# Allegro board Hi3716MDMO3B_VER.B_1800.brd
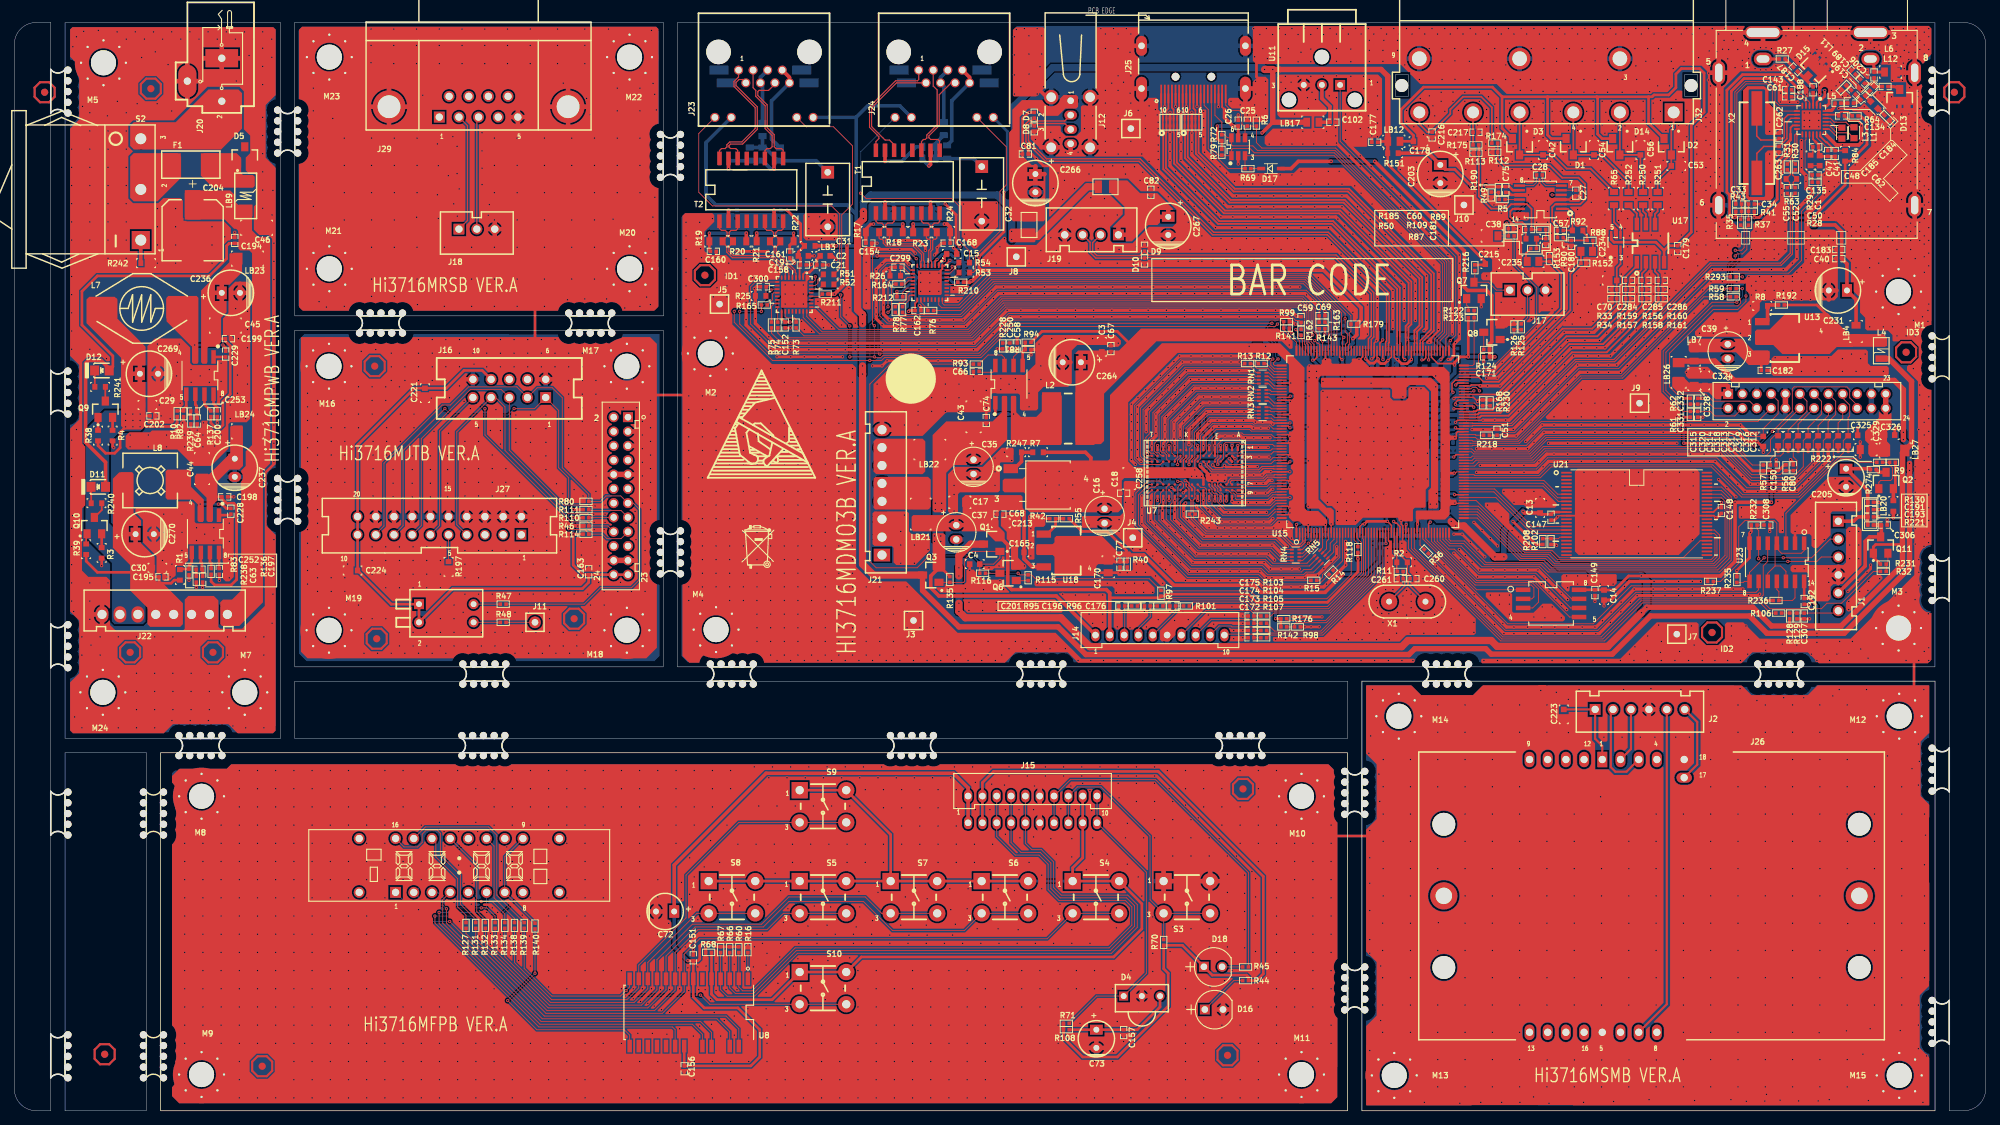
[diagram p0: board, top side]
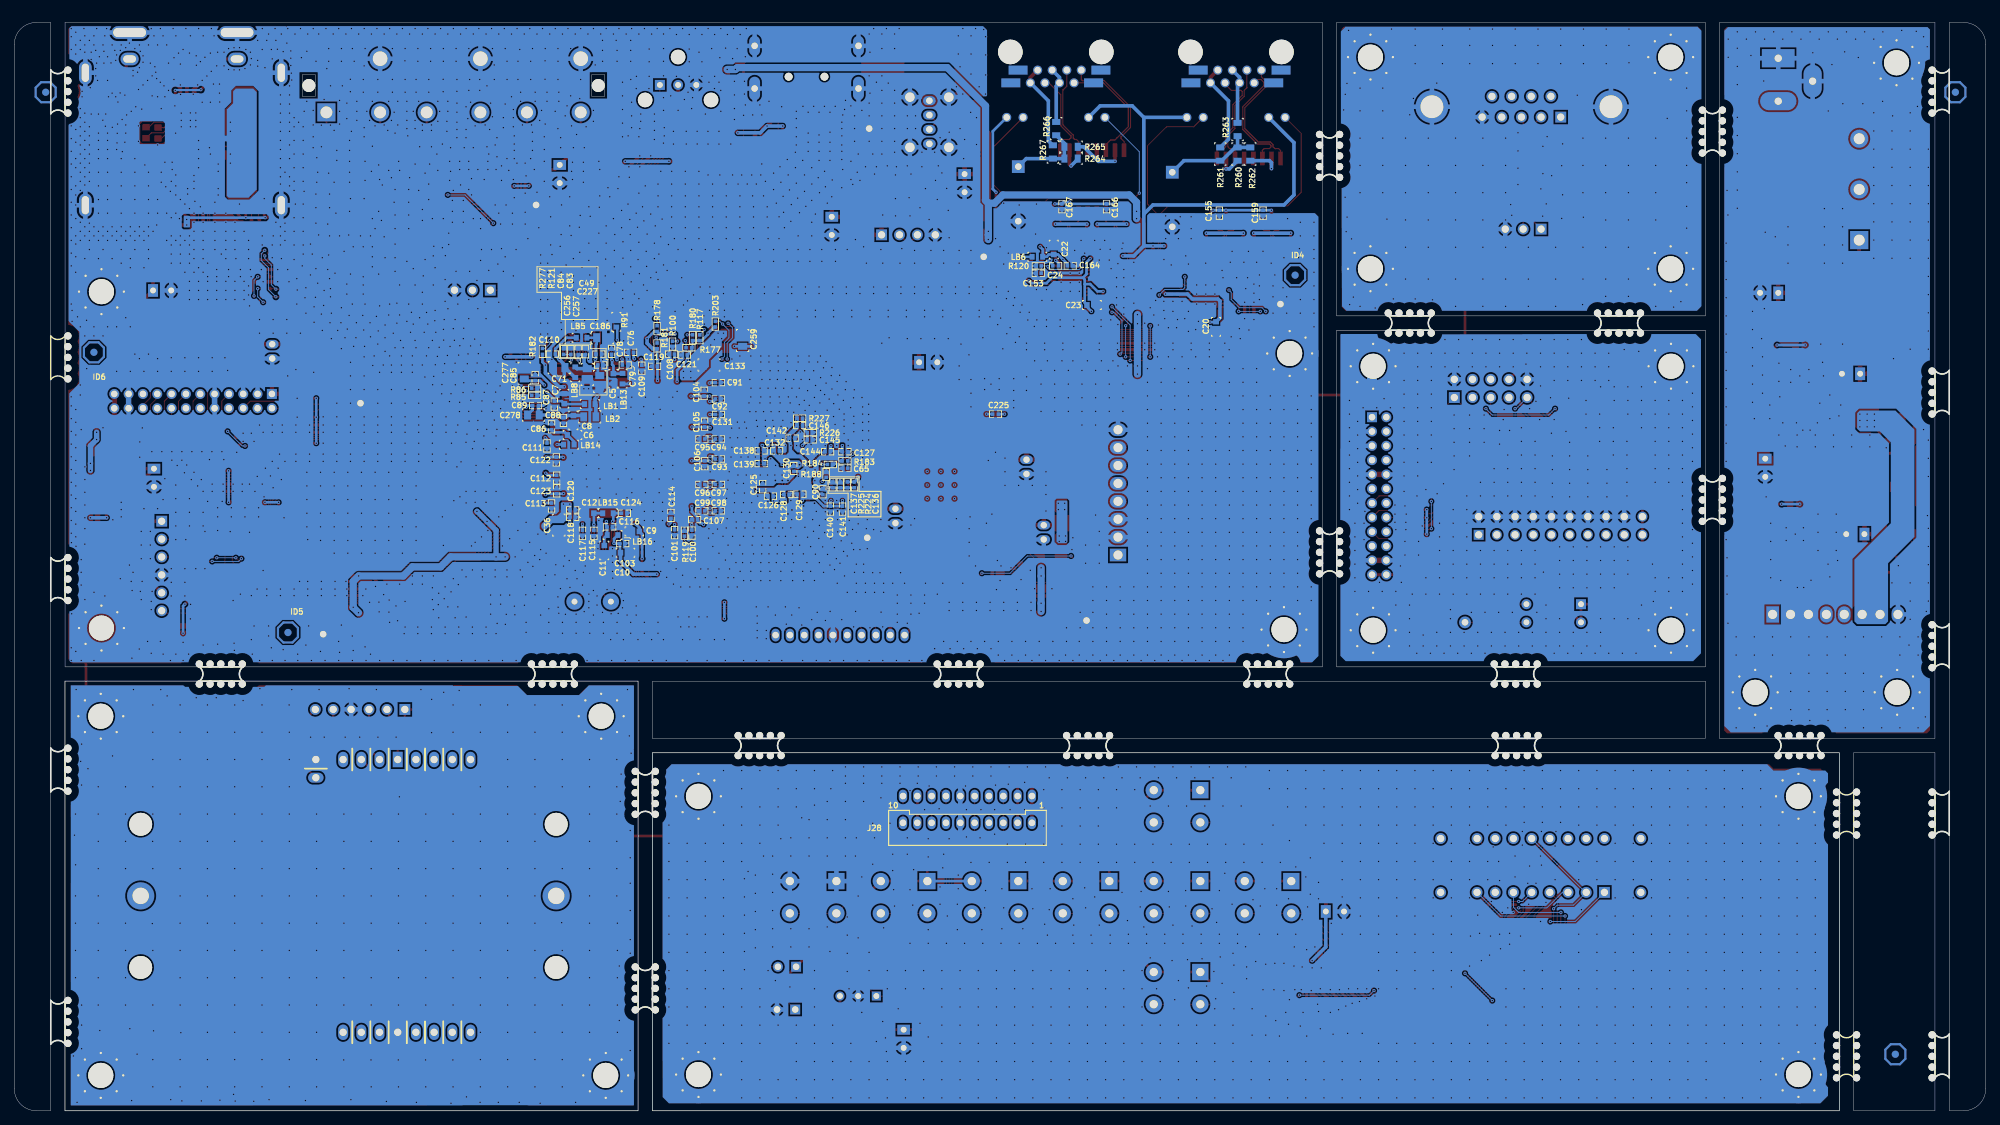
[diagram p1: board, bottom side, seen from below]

Outline 275.18 x 151.99 mm; copper layers: TOP, BOTTOM. Coordinates in mm from the lower left corner of the outline.

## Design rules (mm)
net group DIFFPAIR6: nets TMDS_CLK_N TMDS_CLK_P
net group DIFFPAIR7: nets DM_USB1 DP_USB1
net group DIFFPAIR8: nets DM_USB0 DP_USB0
net group DIFFPAIR10: nets QAM_VINN QAM_VINP
net group DIFFPAIR11: nets TX+_PHY0 TX-_PHY0
net group DIFFPAIR12: nets RX+_PHY0 RX-_PHY0
net group DIFFPAIR15: nets TX+_PHY1 TX-_PHY1
net group DIFFPAIR16: nets RX+_PHY1 RX-_PHY1
net group DIFFPAIR17: nets $12N115 $12N116
net group DIFFPAIR18: nets $12N91 $12N113
net group DIFFPAIR19: nets $12N126 $12N127
net group DIFFPAIR20: nets $12N124 $12N125
net group DIFFPAIR21: nets TMDS_D0_N TMDS_D0_P
net group DIFFPAIR22: nets TMDS_D1_N TMDS_D1_P
net group DIFFPAIR23: nets TMDS_D2_N TMDS_D2_P
net group DIFFPAIR24: nets $17N139 $17N140
net group DIFFPAIR25: nets $17N94 $17N549
net group DDR: nets DDR_ADDR0 DDR_ADDR0_A DDR_ADDR1 DDR_ADDR1_A DDR_ADDR2 DDR_ADDR2_A DDR_ADDR3 DDR_ADDR3_A DDR_ADDR4 DDR_ADDR4_A DDR_ADDR5 DDR_ADDR5_A DDR_ADDR6 DDR_ADDR6_A DDR_ADDR7 DDR_ADDR7_A DDR_ADDR8 DDR_ADDR8_A DDR_ADDR9 DDR_ADDR9_A DDR_ADDR10 DDR_ADDR10_A DDR_ADDR11 DDR_ADDR11_A DDR_ADDR12 DDR_ADDR12_A DDR_ADDR13 DDR_ADDR13_A DDR_ADDR14 DDR_ADDR14_A DDR_BA0 DDR_BA0_A DDR_BA1 DDR_BA1_A DDR_BA2 DDR_BA2_A DDR_CASN DDR_CASN_A DDR_CKE DDR_CKE_A DDR_CKN1 DDR_CKP1 DDR_DM0 DDR_DM1 DDR_DQ0 DDR_DQ1 DDR_DQ2 DDR_DQ3 DDR_DQ4 DDR_DQ5 DDR_DQ6 DDR_DQ7 DDR_DQ8 DDR_DQ9 DDR_DQ10 DDR_DQ11 DDR_DQ12 DDR_DQ13 DDR_DQ14 DDR_DQ15 DDR_DQSN0 DDR_DQSN1 DDR_DQSP0 DDR_DQSP1 DDR_ODT DDR_ODT_A DDR_RASN DDR_RASN_A DDR_RSTN DDR_RSTN_A DDR_WEN DDR_WEN_A
net group NET_3V3: nets 3V3
net group NET_5V0: nets 5V0
net group NET_GND: nets GND
net group POWER: nets 1V2_CTRL 1V2_PLL 1V2_STANDBY 1V5_DDR3 1V8_ETH0 1V8_ETH1 3V3_A_ETH0 3V3_A_ETH1 3V3_MOS 3V3_PLL 3V3_PWR 3V3_T 3V3_TS 5V0_MOS 5V0_PWR 5V0_TS 5V_VIDEO 12V0_PWR

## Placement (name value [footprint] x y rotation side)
C1  100NF  [SC0603]  252 132.69 90 top
C2  100NF  [SC0603]  113.18 119.39 0 top
C3  100NF  [SC0603]  151.8 106.69 90 top
C4  100NF  [SC0603]  134.06 76.34 180 top
C5  100NF  [SC0603]  191.55 102.24 270 bottom
C6  100NF  [SC0603]  197.27 94.37 180 bottom
C7  100NF  [SC0603]  198.41 99.45 90 bottom
C8  100NF  [SC0603]  197.14 96.4 270 bottom
C9  100NF  [SC0603]  188.63 80.91 0 bottom
C10  100NF  [SC0603]  189.87 77.94 180 bottom
C11  100NF  [SC0603]  192.82 78.24 270 bottom
C12  100NF  [SC0603]  194.98 83.45 0 bottom
C13  100NF  [SC0603]  212.98 84.19 90 top
C14  100NF  [SC0603]  221.91 72.02 270 top
C15  100NF  [SC0603]  130.85 119.65 0 top
C16  100UF  [CAPC2-79-217]  152.18 84.07 270 top
C17  2.2UF  [SC0805]  131.99 84.97 180 top
C18  100PF/NC  [SC0402]  154.85 86.24 0 top
C19  100NF  [SC0603]  110.14 119.39 0 top
C20  100NF  [SC0603]  107.43 109.48 270 bottom
C21  100PF/NC  [SC0402]  112.42 118.12 0 top
C22  100NF  [SC0603]  130.08 120.28 90 bottom
C23  100NF  [SC0603]  124.75 112.53 180 bottom
C24  100PF/NC  [SC0402]  129.82 118 0 bottom
C25  100PF/NC  [SC0402]  172.11 137.93 90 top
C26  100PF/NC  [SC0402]  170.84 137.93 90 top
C27  10NF  [HSC0402]  217.97 128.15 90 top
C28  10NF  [HSC0402]  212.89 130.69 180 top
C29  100NF  [SC0603]  18.58 98.56 0 top
C30  100NF  [SC0603]  19.98 75.83 0 top
C31  1NF  [CAP2-300-240]  113.54 127.26 270 top
C32  1NF  [CAP2-300-240]  135.04 128.05 270 top
C33  100PF/NC  [SC0402]  240.7 126.63 180 top
C34  100PF/NC  [SC0402]  242.48 126.63 0 top
C35  100UF  [CAPC2-79-217]  133.89 90.93 270 top
C36  2.2UF  [SC0805]  199.17 81.8 270 bottom
C37  100UF  [CAPC2-79-217]  131.48 81.78 270 top
C38  2.2UF  [SC0805]  206.28 122.18 180 top
C39  100UF  [CAPC2-79-217]  239.18 107.05 270 top
C40  10NF  [HSC0402]  254.67 119.01 180 top
C41  100PF/NC  [SC0402]  254.16 133.69 90 top
C42  100NF  [SC0603]  213.4 134.19 90 top
C43  10UF  [SC1206]  133.89 96.91 90 top
C44  10UF  [SC1206]  26.2 89.67 90 top
C45  10UF  [SC1206]  29.46 109.66 0 top
C46  10UF  [SC1206]  33.82 123.33 0 top
C47  100PF/NC  [SC0402]  253.13 133.69 270 top
C48  100PF/NC  [SC0402]  256.32 140.73 180 top
C49  100PF/NC  [SC0402]  193.58 105.67 180 bottom
C50  100PF/NC  [SC0402]  251.37 130.69 0 top
C51  100PF/NC  [SC0402]  206.97 94.75 90 top
C52  100PF/NC  [SC0402]  248.58 128.53 270 top
C53  100NF  [SC0603]  231.99 131.96 0 top
C54  100NF  [SC0603]  220.51 134.19 90 top
C55  100PF/NC  [SC0402]  247.49 128.51 270 top
C56  100NF  [SC0603]  226.99 134.19 90 top
C57  100PF/NC  [SC0402]  215.81 122.95 180 top
C58  100PF/NC  [SC0402]  139.98 106.82 90 top
C59  100PF/NC  [SC0402]  179.61 110.5 90 top
C60  100PF/NC  [SC0402]  211.37 123.07 180 top
C61  100PF/NC  [SC0402]  247.69 141.61 0 top
C62  100NF  [SC0603]  259.62 140.47 315 top
C63  100PF/NC  [SC0402]  26.29 74.23 270 top
C64  100PF/NC  [SC0402]  25.53 96.32 270 top
C65  100PF/NC  [SC0402]  159.24 89.75 0 bottom
C66  100PF/NC  [SC0402]  134.28 103.26 180 top
C67  100PF/NC  [SC0402]  153.07 106.44 270 top
C68  100PF/NC  [SC0402]  137.58 83.32 180 top
C69  100PF/NC  [SC0402]  182.54 111.03 0 top
C70  100NF  [SC0603]  222.98 115.96 180 top
C71  2.2UF  [SC0805]  199.13 103.79 0 bottom
C72  10UF  [CAPC2-100-200]  90.84 27.82 180 top
C73  10UF  [CAPC2-100-200]  151.04 10.04 270 top
C74  100PF/NC  [SC0402]  135.67 96.4 90 top
C75  100PF/NC  [SC0402]  208.19 128.66 270 top
C76  100PF/NC  [SC0402]  189.14 105.93 0 bottom
C77  100PF/NC  [SC0402]  154.34 76.34 270 top
C78  100PF/NC  [SC0402]  191.81 106.05 90 bottom
C79  100PF/NC  [SC0402]  189.9 104.15 180 bottom
C80  100PF/NC  [SC0402]  248.32 89.8 90 top
C81  100PF/NC  [SC0402]  141.12 133.62 0 top
C82  100PF/NC  [SC0402]  158.65 128.28 90 top
C83  100PF/NC  [SC0402]  195.46 106 90 bottom
C84  100PF/NC  [SC0402]  196.48 106 90 bottom
C85  100PF/NC  [SC0402]  202.47 102.37 90 bottom
C86  100PF/NC  [SC0402]  200.19 95.51 90 bottom
C87  100PF/NC  [SC0402]  199.81 98.69 270 bottom
C88  100PF/NC  [SC0402]  198.53 96.41 270 bottom
C89  100PF/NC  [SC0402]  202.42 98.49 0 bottom
C90  100PF/NC  [SC0402]  162.31 86.45 90 bottom
C91  100PF/NC  [SC0402]  176.92 101.69 180 bottom
C92  100PF/NC  [SC0402]  176.92 99.4 180 bottom
C93  100PF/NC  [SC0402]  176.92 91.02 180 bottom
C94  100PF/NC  [SC0402]  176.92 93.81 180 bottom
C95  100PF/NC  [SC0402]  179.2 93.81 0 bottom
C96  100PF/NC  [SC0402]  179.2 87.46 0 bottom
C97  100PF/NC  [SC0402]  176.92 87.46 180 bottom
C98  100PF/NC  [SC0402]  176.92 83.78 180 bottom
C99  100PF/NC  [SC0402]  179.2 83.78 0 bottom
C100  100PF/NC  [SC0402]  180.6 80.68 270 bottom
C101  100PF/NC  [SC0402]  183.01 80.73 270 bottom
C102  100PF/NC  [SC0402]  184.05 138.06 0 top
C103  100PF/NC  [SC0402]  190.25 79.21 180 bottom
C104  100PF/NC  [SC0402]  178.9 100.21 90 bottom
C105  100PF/NC  [SC0402]  178.82 95.89 90 bottom
C106  100PF/NC  [SC0402]  178.8 90.36 270 bottom
C107  100PF/NC  [SC0402]  180.22 82.56 0 bottom
C108  100PF/NC  [SC0402]  183.42 105.67 0 bottom
C109  100PF/NC  [SC0402]  187.59 103.72 270 bottom
C110  100PF/NC  [SC0402]  200.06 105.67 0 bottom
C111  100PF/NC  [SC0402]  200.82 92.85 270 bottom
C112  100PF/NC  [SC0402]  199.47 88.35 270 bottom
C113  100PF/NC  [SC0402]  200.19 84.46 270 bottom
C114  100PF/NC  [SC0402]  183.52 83.14 90 bottom
C115  100PF/NC  [SC0402]  194.28 80.65 270 bottom
C116  100PF/NC  [SC0402]  192.06 81.54 180 bottom
C117  100PF/NC  [SC0402]  195.87 80.65 270 bottom
C118  100PF/NC  [SC0402]  197.24 82.89 180 bottom
C119  100PF/NC  [SC0402]  185.81 103.97 0 bottom
C120  100PF/NC  [SC0402]  197.24 83.91 180 bottom
C121  100PF/NC  [SC0402]  181.65 105.55 0 bottom
C122  100PF/NC  [SC0402]  199.52 90.89 270 bottom
C123  100PF/NC  [SC0402]  199.47 86.57 90 bottom
C124  100PF/NC  [SC0402]  190.03 83.45 180 bottom
C125  100PF/NC  [SC0402]  170.72 87.15 90 bottom
C126  100PF/NC  [SC0402]  169.63 85.83 0 bottom
C127  100PF/NC  [SC0402]  159.24 92.03 180 bottom
C128  100PF/NC  [SC0402]  167.37 86.06 180 bottom
C129  100PF/NC  [SC0402]  165.52 86.12 0 bottom
C130  100PF/NC  [SC0402]  166.38 89.7 90 bottom
C131  100PF/NC  [SC0402]  176.89 97.24 180 bottom
C132  100PF/NC  [SC0402]  168.77 92.16 180 bottom
C133  2.2UF  [SC0805]  178.22 104.15 180 bottom
C134  100PF/NC  [SC0402]  255.05 138.95 180 top
C135  100PF/NC  [SC0402]  251.46 134.61 0 top
C136  100PF/NC  [SC0402]  157.9 87.41 270 bottom
C137  100PF/NC  [SC0402]  160.92 87.41 90 bottom
C138  100PF/NC  [SC0402]  170.93 92.16 0 bottom
C139  100PF/NC  [SC0402]  170.93 90.38 0 bottom
C140  100PF/NC  [SC0402]  161.27 84.03 270 bottom
C141  100PF/NC  [SC0402]  159.57 84.03 270 bottom
C142  100PF/NC  [SC0402]  166.61 93.94 180 bottom
C143  100PF/NC  [SC0402]  247.68 142.58 0 top
C144  100PF/NC  [SC0402]  161.65 92.03 0 bottom
C145  100PF/NC  [SC0402]  164.08 93.7 180 bottom
C146  100PF/NC  [SC0402]  165.55 95.7 180 bottom
C147  100PF/NC  [SC0402]  214.51 82.89 270 top
C148  100PF/NC  [SC0402]  238.29 83.83 270 top
C149  100PF/NC  [SC0402]  220.64 72.35 270 top
C150  100PF/NC  [SC0402]  245.53 90.18 0 top
C151  100PF/NC  [SC0402]  94.78 21.35 270 top
C152  100PF/NC  [SC0402]  107.6 109.74 270 top
C153  100PF/NC  [SC0402]  132.24 116.98 0 bottom
C154  100PF/NC  [SC0402]  119.28 121.17 180 top
C155  100PF/NC  [SC0402]  106.97 125.36 270 bottom
C156  100PF/NC  [SC0402]  93.51 5.85 270 top
C157  100PF/NC  [SC0402]  154.85 10.91 270 top
C158  100PF/NC  [SC0402]  110.14 118.12 0 top
C159  100PF/NC  [SC0402]  100.87 125.36 270 bottom
C160  100PF/NC  [SC0402]  97.57 120.02 180 top
C161  100PF/NC  [SC0402]  108.24 119.52 270 top
C162  100PF/NC  [SC0402]  126.14 111.76 0 top
C163  100PF/NC  [SC0402]  80.17 75.27 90 top
C164  100PF/NC  [SC0402]  127.79 118 180 bottom
C165  100NF  [SC0603]  140.24 77.99 180 top
C166  100PF/NC  [SC0402]  122.72 126.25 270 bottom
C167  100PF/NC  [SC0402]  128.94 126.25 270 bottom
C168  100PF/NC  [SC0402]  130.21 121.17 180 top
C170  2.2UF  [SC0805]  152.69 75.96 270 top
C171  100PF/NC  [SC0402]  205.52 105.29 180 top
C172  100PF/NC  [SC0402]  172.63 66.05 180 top
C173  100PF/NC  [SC0402]  172.63 67.07 180 top
C174  100PF/NC  [SC0402]  172.63 68.08 180 top
C175  100PF/NC  [SC0402]  172.63 69.1 180 top
C176  100PF/NC  [SC0402]  161.71 70.49 180 top
C177  100PF/NC  [SC0402]  189.9 135.26 180 top
C178  100NF  [SC0603]  196 135.39 0 top
C179  100PF/NC  [SC0402]  232.19 120.41 270 top
C180  100PF/NC  [SC0402]  217.33 121.14 270 top
C181  100PF/NC  [SC0402]  213.77 121.39 270 top
C182  100PF/NC  [SC0402]  244.26 103.39 0 top
C183  100PF/NC  [SC0402]  254.67 120.28 180 top
C184  100PF/NC  [SC0402]  259.31 142.76 225 top
C185  100PF/NC  [SC0402]  258.04 141.49 225 top
C186  2.2UF  [SC0805]  193.08 107.96 180 bottom
C187  100PF/NC  [SC0402]  248.62 145.45 315 top
C188  100PF/NC  [SC0402]  251.09 142.58 270 top
C189  100PF/NC  [SC0402]  257.97 143.77 135 top
C190  100PF/NC  [SC0402]  256.7 142.25 135 top
C191  100PF/NC  [SC0402]  259.12 83.96 0 top
C192  100PF/NC  [SC0402]  249.85 71.13 90 top
C193  100PF/NC  [SC0402]  259.12 82.94 0 top
C194  100PF/NC  [SC0402]  30.77 121.55 270 top
C195  100PF/NC  [SC0402]  20.61 74.56 180 top
C196  100PF/NC  [SC0402]  158.15 70.49 180 top
C197  100PF/NC  [SC0402]  28.61 75.32 270 top
C198  100PF/NC  [SC0402]  29.37 85.73 0 top
C199  100PF/NC  [SC0402]  29.88 107.83 0 top
C200  100PF/NC  [SC0402]  28.32 97.34 270 top
C201  100PF/NC  [SC0402]  154.6 70.49 180 top
C202  100PF/NC  [SC0402]  19.34 97.04 180 top
C203  220UF  [CAPC2-100-250]  199.05 130.83 270 top
C204  220UF  [SCAPC2-280-327]  24.89 122.97 270 top
C205  10UF  [CAPC2-100-200]  255.69 88.4 270 top
C206  100PF/NC  [SC0402]  259.6 144.66 270 top
C213  100NF  [SC0603]  137.7 82.05 0 top
C215  100NF  [SC0603]  206.03 118.25 0 top
C216  100PF/NC  [SC0402]  197.9 136.28 270 top
C217  100PF/NC  [SC0402]  204.03 136.66 0 top
C221  100NF  [SC0603]  57.31 100.21 270 top
C223  100NF  [SC0603]  216.28 55.35 270 top
C224  100NF  [SC0603]  47.21 75.45 180 top
C225  100PF/NC  [SC0402]  138.21 97.29 0 bottom
C227  100PF/NC  [SC0402]  193.33 104.15 180 bottom
C228  100PF/NC  [SC0402]  30.22 83.73 90 top
C229  100PF/NC  [SC0402]  29.5 105.67 90 top
C231  220UF  [CAPC2-100-250]  254.54 114.56 180 top
C234  2.2UF  [SC0805]  219.49 120.02 0 top
C235  2.2UF  [SC0805]  212 118.62 0 top
C236  220UF  [CAPC2-100-250]  30.22 114.23 0 top
C237  220UF  [CAPC2-100-250]  30.77 89.8 270 top
C250  100PF/NC  [SC0402]  138.97 106.82 90 top
C252  100PF/NC  [SC0402]  25.78 75.62 180 top
C253  100PF/NC  [SC0402]  25.02 97.72 180 top
C256  2.2UF  [SC0805]  195.21 102.83 270 bottom
C257  2.2UF  [SC0805]  193.46 101.86 270 bottom
C258  2.2UF  [SC0805]  155.61 88.27 270 top
C259  2.2UF  [SC0805]  173.52 107.58 90 bottom
C260  100PF/NC  [SC0402]  195.24 74.3 0 top
C261  100PF/NC  [SC0402]  193.46 74.3 180 top
C262  100PF/NC  [SC0402]  246.34 136.18 90 top
C263  100PF/NC  [SC0402]  246.34 134.28 270 top
C264  220UF  [CAPC2-100-250]  147.61 104.53 180 top
C266  220UF  [CAPC2-100-250]  142.53 129.55 270 top
C267  220UF  [CAPC2-100-250]  161.07 123.58 270 top
C269  220UF  [CAPC2-100-250]  18.79 102.93 0 top
C270  220UF  [CAPC2-100-250]  18.2 80.53 0 top
C277  2.2UF  [SC0805]  204 103.01 90 bottom
C278  2.2UF  [SC0805]  202.72 97.17 0 bottom
C284  100PF/NC  [SC0402]  225.32 115.96 0 top
C285  100PF/NC  [SC0402]  227.61 115.96 0 top
C286  100PF/NC  [SC0402]  229.9 115.96 0 top
C299  100PF/NC  [SC0402]  123.35 117.81 180 top
C300  100PF/NC  [SC0402]  104.55 115.07 180 top
C306  100PF/NC  [SC0402]  261.02 81.8 0 top
C307  100PF/NC  [SC0402]  249.85 69.1 270 top
C308  100PF/NC  [SC0402]  244.64 81.8 0 top
C312  100NF  [SC0603]  255.98 93.57 270 top
C313  100NF  [SC0603]  250.39 93.57 270 top
C314  100NF  [SC0603]  247.6 93.57 270 top
C315  100NF  [SC0603]  244.13 93.48 270 top
C316  100NF  [SC0603]  254.58 93.57 270 top
C317  100NF  [SC0603]  251.79 93.57 270 top
C318  100NF  [SC0603]  249 93.57 270 top
C319  100NF  [SC0603]  253.19 93.57 270 top
C320  100NF  [SC0603]  246.2 93.57 270 top
C324  100NF  [SC0603]  236 101.99 90 top
C325  100NF  [SC0603]  258.01 94.34 180 top
C326  100NF  [SC0603]  261.78 94.37 0 top
C328  2.2UF  [SC0805]  234.48 102.12 90 top
C329  2.2UF  [SC0805]  258.48 92.34 180 top
C331  100PF/NC  [SC0402]  234.98 97.27 270 top
C332  100PF/NC  [SC0402]  234.99 99.09 90 top
D1  PMOS-GSD  [SOT23]  217.62 134.63 180 top
D2  PMOS-GSD  [SOT23]  231.29 134.63 180 top
D3  PMOS-GSD  [SOT23]  210.12 134.63 180 top
D4  IR  [SEN3-100C]  157.39 16.01 0 top
D5  PMOS-GSD  [SOT23]  32.17 133.49 0 top
D6  DL-E40321BYR2-1W_NAG  [DL-E40321BYR2-1W]  62.11 34.25 0 top
D7  100PF/NC  [SC0402]  142.37 139.03 90 top
D8  100PF/NC  [SC0402]  142.37 137.13 270 top
D9  100PF/NC  [SC0402]  157.76 120.46 90 top
D10  100PF/NC  [SC0402]  157.76 118.68 270 top
D11  LED  [SD0805-LED]  11.72 87.13 180 top
D12  LED  [SD0805-LED]  12.23 103.39 180 top
D13  PMOS-GSD  [SOT23]  263.18 141.49 0 top
D14  PMOS-GSD  [SOT23]  224.11 134.63 180 top
D15  PMOS-GSD  [SOT23]  251.11 145.29 135 top
D16  -  [LED]  167.45 14.13 90 top
D17  D_A  [HSOD323A]  175.42 131.58 180 top
D18  -  [LED]  167.32 20.1 90 top
D19  0.5A  [SMD0805-050]  141.64 123.71 90 top
D20  0.5A  [SMD0805-050]  152.31 129.04 180 top
F1  SSQ4  [SF6127]  24.64 132.14 0 top
ID1  PCB_MARKPOINT_A  [ID-BOARD]  96.39 116.7 0 top
ID2  PCB_MARKPOINT_A  [ID-BOARD]  236.98 66.79 0 top
ID3  PCB_MARKPOINT_A  [ID-BOARD]  264.07 105.93 0 top
ID4  PCB_MARKPOINT_A  [ID-BOARD]  96.39 116.7 180 bottom
ID5  PCB_MARKPOINT_A  [ID-BOARD]  236.98 66.79 180 bottom
ID6  PCB_MARKPOINT_A  [ID-BOARD]  264.07 105.93 180 bottom
J1  TJC3_6A_34HW  [SIP-6P-100]  254.61 76.08 90 top
J2  TJC3_6A_34HW  [SIP-6P-100]  226.92 56.05 180 top
J3  TSW_101_23_F_S  [SIP-1P]  125.51 68.46 0 top
J4  TSW_101_23_F_S  [SIP-1P]  156.12 80.02 0 top
J5  TSW_101_23_F_S  [SIP-1P]  98.44 112.66 0 top
J6  TSW_101_23_F_S  [SIP-1P]  155.86 137.17 0 top
J7  TSW_101_23_F_S  [SIP-1P]  232.07 66.56 0 top
J8  TSW_101_23_F_S  [SIP-1P]  139.86 119.26 0 top
J9  TSW_101_23_F_S  [SIP-1P]  226.86 98.82 0 top
J10  TSW_101_23_F_S  [SIP-1P]  202.35 126.5 0 top
J11  TSW_101_23_F_S  [SIP-1P]  72.68 68.21 180 top
J12  UB31123_K1_4F  [USB4-2007]  147.45 141.07 270 top
J13  -  [JTDA18250]  251.59 135.72 270 top
J14  P2010_10  [SIP-10P_FP]  150.91 66.43 0 top
J15  P2010_10  [SIP-10P_FP]  133.13 43.95 0 top
J16  HU5_100PNA_S53TD20_FA  [IDC10-DTM0]  69.09 100.88 180 top
J17  P2500J_03  [PMR0103-98TQ]  211.24 114.61 180 top
J18  P2500J_03  [PMR0103-98TQ]  64.56 123.13 180 top
J19  P2500J_04  [SIP-4P-100]  150.37 122.33 0 top
J20  DC2026_00  [PWC0103-M-C]  28.95 147 90 top
J21  P2500J_08  [SIP-8P-98]  121.11 77.61 90 top
J22  P2500J_08  [SIP-8P-98]  29.74 69.31 180 top
J23  406533_1  [MJ8-RLY]  101.09 145.34 0 top
J24  406533_1  [MJ8-RLY]  126.24 145.34 0 top
J25  0  [WBC0119-20R]  164.59 147.16 180 top
J26  PF1715-0  [1SMART18-6240]  228.54 30 180 top
J27  HU5_200PNA_S53T_FA  [IDC20-DTM1]  59.34 81.71 180 top
J28  P2010_10  [SIP-10P_FP]  133.13 40.21 0 bottom
J29  DBR40_0918106  [DB9-2RF]  64.8 140.23 180 top
J30  D2008_2X12A  [WBC0212-79T]  85.66 96.86 270 top
J32  0  [VAF9-RF]  231.62 139.44 180 top
J34  D2008_2X12A  [WBC0212-79T]  239.23 100.11 0 top
L1  -  [SL0603A]  256.79 136.59 90 top
L2  4.7UH  [SL2828]  147.12 96.67 270 top
L3  -  [SL0603A]  255.11 136.54 90 top
L4  4.7UH/NC  [HSL1007]  260.61 106.14 90 top
L5  -  [SL0402]  254.54 140.73 180 top
L6  220_100M  [SL0805]  261.91 145.07 180 top
L7  10UH  [SPL1209]  17.78 112.05 180 top
L8  10UH  [SPL0707B]  18.96 88.02 180 top
L9  82N  [HSL0402]  261.4 138.69 135 top
L10  82N  [HSL0402]  255.35 142.88 45 top
L11  -  [SL0402]  256.7 145.04 315 top
L12  -  [SL0402]  261.15 143.04 180 top
LB1  BLM18HG601SN1D  [SL0603]  194.85 98.69 0 bottom
LB2  220_100M  [SL0805]  194.85 96.91 180 bottom
LB3  BLM18HG601SN1D  [SL0603]  111.03 120.79 180 top
LB4  220_100M  [SL0805]  257.08 108.85 90 top
LB5  BLM18HG601SN1D  [SL0603]  196 107.96 0 bottom
LB6  BLM18HG601SN1D  [SL0603]  132.37 119.26 180 bottom
LB7  220_100M  [SL0805]  234.48 105.55 270 top
LB8  BLM18HG601SN1D  [SL0603]  196.88 103.14 270 bottom
LB9  FCFBMJ4516HS720NT  [SL1806]  32.29 127.77 270 top
LB12  220_100M  [SL0805]  192.57 135.39 180 top
LB13  BLM18HG601SN1D  [SL0603]  190.28 102.24 90 bottom
LB14  BLM18HG601SN1D  [SL0603]  197.78 93.02 180 bottom
LB15  BLM18HG601SN1D  [SL0603]  192.31 83.45 0 bottom
LB16  BLM18HG601SN1D  [SL0603]  191.68 80.4 0 bottom
LB17  220_100M  [SL0805]  181.26 138.06 0 top
LB20  BLM18HG601SN1D  [SL0603]  262.29 84.46 90 top
LB21  FCFBMH3225HM601NT  [SL1210]  126.53 83.33 270 top
LB22  FCFBMH3225HM601NT  [SL1210]  127.8 92.34 0 top
LB23  LB  [SL1206]  32.55 119.01 180 top
LB24  LB  [SL1206]  32.55 94.88 180 top
LB26  LB  [SL1206]  232.32 103.13 90 top
LB27  LB  [SL1206]  262.55 92.21 180 top
M1  138MIL_STAR_HOLE_APPLY_TO_M3  [HOLE138-8STAR]  263.02 114.4 0 top
M2  138MIL_STAR_HOLE_APPLY_TO_M3  [HOLE138-8STAR]  97.16 105.76 0 top
M3  138MIL_STAR_HOLE_APPLY_TO_M3  [HOLE138-8STAR]  263.02 67.41 0 top
M4  138MIL_STAR_HOLE_APPLY_TO_M3  [HOLE138-8STAR]  97.95 67.19 0 top
M5  138MIL_STAR_HOLE_APPLY_TO_M3  [HOLE138-8STAR]  12.44 146.36 0 top
M7  138MIL_STAR_HOLE_APPLY_TO_M3  [HOLE138-8STAR]  32.17 58.43 0 top
M8  138MIL_STAR_HOLE_APPLY_TO_M3  [HOLE138-8STAR]  26.13 43.91 0 top
M9  138MIL_STAR_HOLE_APPLY_TO_M3  [HOLE138-8STAR]  26.13 5.05 0 top
M10  138MIL_STAR_HOLE_APPLY_TO_M3  [HOLE138-8STAR]  179.68 43.91 0 top
M11  138MIL_STAR_HOLE_APPLY_TO_M3  [HOLE138-8STAR]  179.68 5.05 0 top
M12  138MIL_STAR_HOLE_APPLY_TO_M3  [HOLE138-8STAR]  263.11 55.09 180 top
M13  138MIL_STAR_HOLE_APPLY_TO_M3  [HOLE138-8STAR]  192.63 4.93 180 top
M14  138MIL_STAR_HOLE_APPLY_TO_M3  [HOLE138-8STAR]  193.26 55.09 180 top
M15  138MIL_STAR_HOLE_APPLY_TO_M3  [HOLE138-8STAR]  263.11 4.93 180 top
M16  138MIL_STAR_HOLE_APPLY_TO_M3  [HOLE138-8STAR]  43.93 103.97 0 top
M17  138MIL_STAR_HOLE_APPLY_TO_M3  [HOLE138-8STAR]  85.5 103.97 0 top
M18  138MIL_STAR_HOLE_APPLY_TO_M3  [HOLE138-8STAR]  85.5 67.1 0 top
M19  138MIL_STAR_HOLE_APPLY_TO_M3  [HOLE138-8STAR]  43.93 67.1 0 top
M20  138MIL_STAR_HOLE_APPLY_TO_M3  [HOLE138-8STAR]  85.88 117.59 0 top
M21  138MIL_STAR_HOLE_APPLY_TO_M3  [HOLE138-8STAR]  43.97 117.59 0 top
M22  138MIL_STAR_HOLE_APPLY_TO_M3  [HOLE138-8STAR]  85.88 147.15 0 top
M23  138MIL_STAR_HOLE_APPLY_TO_M3  [HOLE138-8STAR]  43.97 147.15 0 top
M24  138MIL_STAR_HOLE_APPLY_TO_M3  [HOLE138-8STAR]  12.36 58.43 0 top
NOREF  -  [unnamed]  200 60.99 180 top
NOREF#2  -  [unnamed#2]  50.3 103.99 180 top
NOREF#3  -  [unnamed]  38.15 136.76 270 top
NOREF#4  -  [unnamed#2]  171.51 44.95 180 top
NOREF#5  -  [unnamed]  25.98 51 0 top
NOREF#6  -  [unnamed#2]  50.58 65.92 180 top
NOREF#7  -  [unnamed]  91.58 133.36 270 top
NOREF#8  -  [unnamed]  65.6 60.99 0 top
NOREF#9  -  [unnamed]  80.39 110.01 180 top
NOREF#10  -  [unnamed]  187.1 44.4 270 top
NOREF#11  -  [unnamed]  38.15 85.31 270 top
NOREF#12  -  [unnamed]  19.42 7.6 90 top
NOREF#13  -  [unnamed#2]  27.72 64.02 0 top
NOREF#14  -  [unnamed#3]  269.1 142.34 270 top
NOREF#15  -  [unnamed#2]  34.6 6.21 180 top
NOREF#16  -  [unnamed]  187.1 17.08 270 top
NOREF#17  -  [#4]  201.97 196.91 0 top
NOREF#18  -  [unnamed#2]  4.23 142.25 0 top
NOREF#19  -  [unnamed#2]  12.61 7.88 0 top
NOREF#20  -  [unnamed]  91.58 77.99 270 top
NOREF#21  -  [unnamed#3]  6.08 41.51 90 top
NOREF#22  -  [#4]  77.77 239.83 0 top
NOREF#23  -  [unnamed]  143.36 60.99 180 top
NOREF#24  -  [#4]  202.23 223.83 0 top
NOREF#25  -  [unnamed]  171.14 51 0 top
NOREF#26  -  [unnamed#3]  6.08 100.31 90 top
NOREF#27  -  [#4]  0 3.05 0 top
NOREF#28  -  [unnamed#3]  269.1 12.4 270 top
NOREF#29  -  [#4]  -111.15 -126.32 0 top
NOREF#30  -  [unnamed#2]  19.05 142.75 0 top
NOREF#31  -  [unnamed#3]  6.08 64.87 90 top
NOREF#32  -  [#4]  5.08 0 90 top
NOREF#33  -  [unnamed#2]  78.14 68.72 180 top
NOREF#34  -  [unnamed#2]  270.8 142.25 0 top
NOREF#35  -  [#4]  0 0 0 top
NOREF#36  -  [unnamed#3]  269.1 47.64 270 top
NOREF#37  -  [#4]  274.11 151.26 0 top
NOREF#38  -  [unnamed]  51.18 110.01 180 top
NOREF#39  -  [unnamed]  65.48 51 0 top
NOREF#40  -  [#4]  106.34 78.86 0 top
NOREF#41  -  [unnamed]  246.36 60.99 180 top
NOREF#42  -  [unnamed#3]  6.08 142.34 90 top
NOREF#43  -  [unnamed#2]  169.35 7.73 180 top
NOREF#44  -  [unnamed#2]  16.17 64.02 0 top
NOREF#45  -  [unnamed]  100.15 60.99 0 top
NOREF#46  -  [#4]  104.81 92.85 0 top
NOREF#47  -  [#4]  70.65 208.34 0 top
NOREF#48  -  [unnamed#3]  269.1 105.21 270 top
NOREF#49  -  [unnamed]  125.29 51 0 top
NOREF#50  -  [unnamed]  19.42 41.51 90 top
NOREF#51  -  [#4]  125.64 102.47 0 top
NOREF#52  -  [unnamed#3]  269.1 74.26 270 top
NOREF#53  -  [unnamed#3]  6.08 7.6 90 top
NOREF#54  -  [unnamed#2]  12.61 7.88 180 bottom
NOREF#55  -  [unnamed#2]  4.23 142.25 180 bottom
NOREF#56  -  [unnamed#2]  270.8 142.25 180 bottom
Q1  PMOS-GSD  [SOT23]  136.43 79.13 90 top
Q2  PMOS-GSD  [SOT23]  261.28 88.02 0 top
Q3  PMOS-GSD  [SOT23]  127.93 74.81 90 top
Q6  PMOS-GSD  [SOT23]  138.72 75.07 90 top
Q7  PMOS-GSD  [SOT23]  203.74 114.56 0 top
Q8  PMOS-GSD  [SOT23]  206.26 108.72 90 top
Q9  PMOS-GSD  [SOT23]  12.7 97.97 0 top
Q10  PMOS-GSD  [SOT23]  11.17 81.72 0 top
Q11  PMOS-GSD  [SOT23]  260.51 79 0 top
R1  5.1K  [SR0603]  23.11 74.84 270 top
R2  5.1K  [SR0603]  193.71 76.59 0 top
R3  5.1K  [SR0603]  12.19 77.91 270 top
R4  5.1K  [SR0603]  13.71 94.29 270 top
R5  2.2K/NC  [SR0402]  207.68 127.26 180 top
R6  2.2K/NC  [SR0402]  173.38 137.93 90 top
R7  5.1K  [SR0603]  142.9 91.96 0 top
R8  5.1K  [SR0603]  243.99 112.41 180 top
R9  2.2K/NC  [SR0402]  262.16 90.56 180 top
R10  2.2K/NC  [SR0402]  22.73 97.34 270 top
R11  2.2K/NC  [SR0402]  193.46 75.32 180 top
R12  2.2K/NC  [SR0402]  174.05 104.35 180 top
R13  2.2K/NC  [SR0402]  172.14 104.35 180 top
R14  2.2K/NC  [SR0402]  183.81 75.19 225 top
R15  2.2K/NC  [SR0402]  181.39 74.08 180 top
R16  2.2K/NC  [SR0402]  102.4 22.49 90 top
R17  75  [SR0805]  119.79 122.69 180 top
R18  75  [SR0805]  123.09 122.69 0 top
R19  75  [SR0805]  97.94 121.42 180 top
R20  75  [SR0805]  101.25 121.42 0 top
R21  75  [SR0805]  104.55 121.42 0 top
R22  75  [SR0805]  107.85 121.42 180 top
R23  75  [SR0805]  126.39 122.69 0 top
R24  75  [SR0805]  129.69 122.69 180 top
R25  5.1K  [SR0603]  104.18 113.8 180 top
R26  5.1K  [SR0603]  122.97 116.62 180 top
R27  2.2K/NC  [SR0402]  246.78 146.89 0 top
R28  2.2K/NC  [SR0402]  251.37 129.68 0 top
R29  5.1K  [SR0603]  250.73 132.72 270 top
R30  2.2K/NC  [SR0402]  248.61 131.82 270 top
R31  2.2K/NC  [SR0402]  247.49 131.82 270 top
R32  2.2K/NC  [SR0402]  260.88 75.32 0 top
R33  2.2K/NC  [SR0402]  223.28 114.69 0 top
R34  2.2K/NC  [SR0402]  223.28 113.42 0 top
R35  2.2K/NC  [SR0402]  240.98 124.09 90 top
R36  2.2K/NC  [SR0402]  197.09 78.11 315 top
R37  2.2K/NC  [SR0402]  242.07 124.09 90 top
R38  5.1K  [SR0603]  11.68 94.29 90 top
R39  5.1K  [SR0603]  10.03 78.42 90 top
R40  2.2K/NC  [SR0402]  155.36 76.34 270 top
R41  2.2K/NC  [SR0402]  242.48 125.61 0 top
R42  2.2K/NC  [SR0402]  144.94 82.69 0 top
R43  2.2K/NC  [SR0402]  240.7 125.61 180 top
R44  2.2K/NC  [SR0402]  171.87 18.17 180 top
R45  2.2K/NC  [SR0402]  171.87 20.08 0 top
R46  2.2K/NC  [SR0402]  79.79 81.67 0 top
R47  2.2K/NC  [SR0402]  68.24 70.75 180 top
R48  2.2K/NC  [SR0402]  68.24 68.21 0 top
R49  2.2K/NC  [SR0402]  206.16 127.9 90 top
R50  2.2K/NC  [SR0402]  208.95 122.18 180 top
R51  5.1K  [SR0603]  113.67 116.81 0 top
R52  5.1K  [SR0603]  113.67 115.41 0 top
R53  5.1K  [SR0603]  132.61 117.06 0 top
R54  5.1K  [SR0603]  132.59 118.46 0 top
R55  2.2K/NC  [SR0402]  146.85 82.69 0 top
R56  2.2K/NC  [SR0402]  247.31 89.8 270 top
R57  2.2K/NC  [SR0402]  244.13 89.77 90 top
R58  2.2K/NC  [SR0402]  239.94 113.67 0 top
R59  2.2K/NC  [SR0402]  239.94 114.82 0 top
R60  2.2K/NC  [SR0402]  101.13 22.49 90 top
R61  2.2K/NC  [SR0402]  233.96 97.27 90 top
R62  2.2K/NC  [SR0402]  233.97 99.09 270 top
R63  5.1K  [SR0603]  248.05 130.14 0 top
R64  2.2K/NC  [SR0402]  256.96 138.95 0 top
R65  75  [SR0805]  223.29 127.39 270 top
R66  2.2K/NC  [SR0402]  99.86 22.49 90 top
R67  2.2K/NC  [SR0402]  98.59 22.49 90 top
R68  2.2K/NC  [SR0402]  96.91 22.11 0 top
R69  2.2K/NC  [SR0402]  172.2 131.58 180 top
R70  2.2K/NC  [SR0402]  160.44 23.5 270 top
R71  2.2K/NC  [SR0402]  146.85 12.2 180 top
R72  2.2K/NC  [SR0402]  168.56 135.9 270 top
R73  2.2K/NC  [SR0402]  109.12 109.74 90 top
R74  2.2K/NC  [SR0402]  106.58 109.74 90 top
R75  2.2K/NC  [SR0402]  105.69 109.74 90 top
R76  2.2K/NC  [SR0402]  127.92 111.76 180 top
R77  2.2K/NC  [SR0402]  123.99 111.9 90 top
R78  2.2K/NC  [SR0402]  122.97 111.9 90 top
R79  2.2K/NC  [SR0402]  168.56 133.87 90 top
R80  2.2K/NC  [SR0402]  79.79 85.1 0 top
R81  2.2K/NC  [SR0402]  141.51 106.31 180 top
R82  2.2K/NC  [SR0402]  23.62 97.34 270 top
R83  2.2K/NC  [SR0402]  24.38 75.24 270 top
R84  5.1K  [SR0603]  255.56 133.36 270 top
R85  2.2K/NC  [SR0402]  202.55 99.91 180 bottom
R86  2.2K/NC  [SR0402]  202.55 100.92 180 bottom
R87  2.2K/NC  [SR0402]  212.07 120.42 180 top
R88  2.2K/NC  [SR0402]  219.95 121.55 180 top
R89  2.2K/NC  [SR0402]  213.36 123.08 0 top
R90  2.2K/NC  [SR0402]  215.81 121.94 180 top
R91  5.1K  [SR0603]  191.14 110.19 270 bottom
R92  5.1K  [SR0603]  218.22 122.95 180 top
R93  2.2K/NC  [SR0402]  134.28 104.28 180 top
R94  2.2K/NC  [SR0402]  141.51 107.32 0 top
R95  2.2K/NC  [SR0402]  156.37 70.49 0 top
R96  2.2K/NC  [SR0402]  159.93 70.49 0 top
R97  2.2K/NC  [SR0402]  160.06 72.27 90 top
R98  2.2K/NC  [SR0402]  179.11 67.57 0 top
R99  2.2K/NC  [SR0402]  177.58 110.19 0 top
R100  2.2K/NC  [SR0402]  183.3 107.07 270 bottom
R101  2.2K/NC  [SR0402]  163.61 70.49 0 top
R102  2.2K/NC  [SR0402]  214.5 79.49 270 top
R103  2.2K/NC  [SR0402]  174.41 69.1 0 top
R104  2.2K/NC  [SR0402]  174.41 68.08 0 top
R105  2.2K/NC  [SR0402]  174.41 67.07 0 top
R106  2.2K/NC  [SR0402]  246.29 69.5 0 top
R107  2.2K/NC  [SR0402]  174.41 66.05 0 top
R108  2.2K/NC  [SR0402]  146.85 11.31 180 top
R109  5.1K  [SR0603]  211.74 121.79 0 top
R110  2.2K/NC  [SR0402]  79.79 82.81 180 top
R111  2.2K/NC  [SR0402]  79.79 83.96 180 top
R112  2.2K/NC  [SR0402]  206.66 133.87 180 top
R113  2.2K/NC  [SR0402]  204.03 133.74 180 top
R114  2.2K/NC  [SR0402]  79.79 80.53 180 top
R115  2.2K/NC  [SR0402]  141.51 74.43 270 top
R116  2.2K/NC  [SR0402]  135.16 75.07 0 top
R117  2.2K/NC  [SR0402]  179.49 107.96 270 bottom
R118  2.2K/NC  [SR0402]  187.54 78.37 270 top
R119  2.2K/NC  [SR0402]  181.64 80.66 90 bottom
R120  2.2K/NC  [SR0402]  132.24 117.99 0 bottom
R121  2.2K/NC  [SR0402]  197.5 106.03 90 bottom
R122  2.2K/NC  [SR0402]  203.36 111.77 0 top
R123  2.2K/NC  [SR0402]  203.36 110.75 0 top
R124  2.2K/NC  [SR0402]  205.52 106.31 0 top
R125  2.2K/NC  [SR0402]  210.35 109.48 90 top
R126  2.2K/NC  [SR0402]  209.33 109.48 270 top
R127  2.2K/NC  [SR0402]  63.05 25.87 90 top
R128  2.2K/NC  [SR0402]  247.81 69.1 270 top
R129  2.2K/NC  [SR0402]  248.83 69.1 90 top
R130  2.2K/NC  [SR0402]  259.12 84.97 180 top
R131  2.2K/NC  [SR0402]  64.4 25.87 90 top
R132  2.2K/NC  [SR0402]  65.75 25.87 90 top
R133  2.2K/NC  [SR0402]  67.11 25.87 90 top
R134  2.2K/NC  [SR0402]  68.46 25.87 90 top
R135  2.2K/NC  [SR0402]  130.59 74.2 270 top
R136  2.2K/NC  [SR0402]  27.47 75.32 90 top
R137  2.2K/NC  [SR0402]  27.43 97.34 90 top
R138  2.2K/NC  [SR0402]  69.81 25.87 90 top
R139  2.2K/NC  [SR0402]  71.17 25.87 90 top
R140  2.2K/NC  [SR0402]  72.68 25.79 90 top
R141  2.2K/NC  [SR0402]  177.58 109.31 0 top
R142  2.2K/NC  [SR0402]  177.2 67.57 180 top
R143  2.2K/NC  [SR0402]  182.54 109.23 0 top
R151  5.1K  [SR0603]  192.44 133.74 0 top
R152  2.2K/NC  [SR0402]  219.09 118.37 0 top
R153  2.2K/NC  [SR0402]  214.29 119.02 90 top
R156  2.2K/NC  [SR0402]  227.61 114.69 180 top
R157  2.2K/NC  [SR0402]  225.32 113.42 180 top
R158  2.2K/NC  [SR0402]  227.61 113.42 180 top
R159  2.2K/NC  [SR0402]  225.32 114.69 180 top
R160  2.2K/NC  [SR0402]  229.9 114.69 180 top
R161  2.2K/NC  [SR0402]  229.9 113.42 180 top
R162  2.2K/NC  [SR0402]  179.61 108.72 90 top
R163  2.2K/NC  [SR0402]  182.54 110.14 180 top
R164  2.2K/NC  [SR0402]  123.47 115.46 0 top
R165  2.2K/NC  [SR0402]  104.68 112.53 0 top
R168  2.2K/NC  [SR0402]  204.98 98.87 270 top
R174  560  [HSR0402]  206.66 135.14 0 top
R175  560  [HSR0402]  204.03 134.89 180 top
R176  2.2K/NC  [SR0402]  177.2 68.72 180 top
R177  2.2K/NC  [SR0402]  181.01 106.56 180 bottom
R178  2.2K/NC  [SR0402]  185.46 109.23 270 bottom
R179  2.2K/NC  [SR0402]  186.98 109.86 0 top
R180  2.2K/NC  [SR0402]  180.5 107.96 270 bottom
R181  2.2K/NC  [SR0402]  185.46 106.82 270 bottom
R182  2.2K/NC  [SR0402]  201.46 106.05 270 bottom
R183  2.2K/NC  [SR0402]  159.24 90.76 180 bottom
R184  2.2K/NC  [SR0402]  161.27 90.26 180 bottom
R185  2.2K/NC  [SR0402]  208.96 123.2 0 top
R188  2.2K/NC  [SR0402]  161.86 88.86 270 bottom
R190  2.2K/NC  [SR0402]  207.17 128.65 90 top
R192  2.2K/NC  [SR0402]  246.66 112.53 0 top
R197  5.1K  [SR0603]  60.61 75.96 270 top
R203  2.2K/NC  [SR0402]  177.33 109.86 270 bottom
R208  2.2K/NC  [SR0402]  213.36 79.49 90 top
R210  2.2K/NC  [SR0402]  132.11 115.71 0 top
R211  2.2K/NC  [SR0402]  113.18 114.06 0 top
R212  2.2K/NC  [SR0402]  123.61 113.67 180 top
R216  2.2K/NC  [SR0402]  203.87 117.74 270 top
R218  2.2K/NC  [SR0402]  205.5 94.34 180 top
R221  2.2K/NC  [SR0402]  259.12 81.8 0 top
R222  2.2K/NC  [SR0402]  260.39 90.56 0 top
R224  2.2K/NC  [SR0402]  158.91 87.41 90 bottom
R225  2.2K/NC  [SR0402]  159.88 87.41 270 bottom
R226  2.2K/NC  [SR0402]  164.08 94.71 0 bottom
R227  2.2K/NC  [SR0402]  165.55 96.72 0 bottom
R228  2.2K/NC  [SR0402]  137.96 106.82 270 top
R230  2.2K/NC  [SR0402]  206 98.87 270 top
R231  2.2K/NC  [SR0402]  260.88 76.34 0 top
R232  2.2K/NC  [SR0402]  242.86 81.8 180 top
R235  2.2K/NC  [SR0402]  240.45 74.18 90 top
R236  2.2K/NC  [SR0402]  245.91 71.26 180 top
R237  2.2K/NC  [SR0402]  236.76 73.92 0 top
R238  2.2K/NC  [SR0402]  25.4 74.23 270 top
R239  2.2K/NC  [SR0402]  24.64 96.32 270 top
R240  5.1K  [SR0603]  11.47 84.85 0 top
R241  5.1K  [SR0603]  11.97 101.1 0 top
R242  5.1K  [SR0603]  18.39 118.37 180 top
R243  2.2K/NC  [SR0402]  164.43 83.32 180 top
R247  5.1K  [SR0603]  139.85 91.96 180 top
R250  75  [SR0805]  227.36 127.39 270 top
R251  75  [SR0805]  229.39 127.39 270 top
R252  75  [SR0805]  225.32 127.39 270 top
R260  75  [SR0805]  104.43 133.61 270 bottom
R261  75  [SR0805]  106.84 133.61 90 bottom
R262  75  [SR0805]  102.65 133.61 270 bottom
R263  75  [SR0805]  104.43 137.04 90 bottom
R264  75  [SR0805]  127.67 132.98 180 bottom
R265  75  [SR0805]  127.67 134.63 180 bottom
R266  75  [SR0805]  129.74 137.17 90 bottom
R267  75  [SR0805]  130.21 133.91 90 bottom
R274  2.2K/NC  [SR0402]  259.5 89.54 180 top
R277  2.2K/NC  [SR0402]  198.5 106.03 90 bottom
R293  2.2K/NC  [SR0402]  239.94 116.47 0 top
RN1  51  [SRN8-0804]  174.25 102.32 270 top
RN2  51  [SRN8-0804]  174.25 99.91 270 top
RN3  51  [SRN8-0804]  174.25 97.49 270 top
RN4  51  [SRN8-0804]  178.85 77.61 270 top
RN5  51  [SRN8-0804]  182.41 77.35 315 top
S1  EPG102A  [DSW4-LP]  60.3 69.48 270 top
S2  RA22KKFR0FL_D1  [PSW3-RA]  17.65 121.6 90 top
S3  DTS_61N_K  [SW4-PUSH]  163.68 29.81 0 top
S4  DTS_61N_K  [SW4-PUSH]  150.98 29.81 0 top
S5  DTS_61N_K  [SW4-PUSH]  112.88 29.81 0 top
S6  DTS_61N_K  [SW4-PUSH]  138.28 29.81 0 top
S7  DTS_61N_K  [SW4-PUSH]  125.58 29.81 0 top
S8  DTS_61N_K  [SW4-PUSH]  100.18 29.81 0 top
S9  DTS_61N_K  [SW4-PUSH]  112.88 42.51 0 top
S10  DTS_61N_K  [SW4-PUSH]  112.88 17.11 0 top
T1  H1102T  [STFM16-50-285]  124.72 129.76 0 top
T2  H1102T  [STFM16-50-285]  102.87 128.62 0 top
U2  AZ1045-04F  [DFN2510P10E]  164.37 138.06 0 top
U3  KSZ8041NL  [MLF32-050-0505LB]  108.87 113.99 180 top
U4  KSZ8041NL  [MLF32-050-0505LB]  127.79 115.64 180 top
U5  AZ1045-04F  [DFN2510P10E]  161.32 138.06 0 top
U6  MP1482  [SOIC8N]  26.67 80.58 180 top
U7  MT41J64M16LA-15E  [BGA96-32-1609F]  164.78 89.06 180 top
U8  PT6964  [SOP28-50-300]  94.14 13.73 180 top
U9  -  [SGM8903]  213.02 127.26 90 top
U10  LM1117-ADJ  [TO-252]  142.47 87.39 270 top
U11  GP1FAV50TK0F  [LASER3-1214]  182.53 143.27 180 top
U12  FMS6141  [FMS6141_SC70]  223.56 121.29 0 top
U13  LM1117-ADJ  [SOT223A]  247.14 107.92 270 top
U14  AZC099-04S  [SOT23A-6L]  170.84 134.63 0 top
U15  HI3716MV300  [QFP216HC-040-2424L]  189.62 93.43 0 top
U16  8PIN-SPIFLASH  [SO8W]  214.51 70.85 270 top
U17  FMS6363  [SOP8-50-173]  228.38 121.17 0 top
U18  LM1117-ADJ  [SOT223A]  146.85 78.24 270 top
U19  MP1482  [SOIC8N]  138.85 101.48 0 top
U20  MP1482  [SOIC8N]  25.91 102.67 180 top
U21  0  [SOP48-20-720B]  226.47 83.35 270 top
U22  -  [FN24-050-0404LH]  250.84 138.36 180 top
U23  SN74HC125DR  [SOP14-50-150]  246.03 76.6 180 top
X1  28.8MHZ  [XTAL2-200A]  194.44 71.1 180 top
X2  16MHZ  [SX2-1205]  243.24 135.14 270 top

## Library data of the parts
C1-C15 C19 C20 C22 C23 C29 C30 C42 C53 C54 C56 C62 C70 C165 C178 C213 C215 C221 C223 C224 C312-C320 C324-C326 = SC0603
C16 C35 C37 C39 = CAPC2-79-217
C17 C36 C38 C71 C133 C170 C186 C234 C235 C256-C259 C277 C278 C328 C329 = SC0805
C18 C21 C24-C26 C33 C34 C41 C47-C52 C55 C57-C61 C63-C69 C74-C132 C134-C164 C166-C168 C171-C177 C179-C185 C187-C202 C206 C216 C217 C225 C227-C229 C250 C252 C253 C260-C263 C284-C286 C299 C300 C306-C308 C331 C332 D7-D10 = SC0402
C27 C28 C40 = HSC0402
C31 C32 = CAP2-300-240
C43-C46 = SC1206
C72 C73 C205 = CAPC2-100-200
C203 C231 C236 C237 C264 C266 C267 C269 C270 = CAPC2-100-250
C204 = SCAPC2-280-327
D1-D3 D5 D13-D15 Q1-Q3 Q6-Q11 = SOT23
D4 = SEN3-100C
D6 = DL-E40321BYR2-1W
D11 D12 = SD0805-LED
D16 D18 = LED
D17 = HSOD323A
D19 D20 = SMD0805-050
F1 = SF6127
ID1-ID6 = ID-BOARD
J1 J2 = SIP-6P-100
J3-J11 = SIP-1P
J12 = USB4-2007
J13 = JTDA18250
J14 J15 J28 = SIP-10P_FP
J16 = IDC10-DTM0
J17 J18 = PMR0103-98TQ
J19 = SIP-4P-100
J20 = PWC0103-M-C
J21 J22 = SIP-8P-98
J23 J24 = MJ8-RLY
J25 = WBC0119-20R
J26 = 1SMART18-6240
J27 = IDC20-DTM1
J29 = DB9-2RF
J30 J34 = WBC0212-79T
J32 = VAF9-RF
L1 L3 = SL0603A
L2 = SL2828
L4 = HSL1007
L5 L11 L12 = SL0402
L6 LB2 LB4 LB7 LB12 LB17 = SL0805
L7 = SPL1209
L8 = SPL0707B
L9 L10 = HSL0402
LB1 LB3 LB5 LB6 LB8 LB13-LB16 LB20 = SL0603
LB9 = SL1806
LB21 LB22 = SL1210
LB23 LB24 LB26 LB27 = SL1206
M1-M5 M7-M24 = HOLE138-8STAR
R1-R4 R7 R8 R25 R26 R29 R38 R39 R51-R54 R63 R84 R91 R92 R109 R151 R197 R240-R242 R247 = SR0603
R5 R6 R9-R16 R27 R28 R30-R37 R40-R50 R55-R62 R64 R66-R83 R85-R90 R93-R108 R110-R143 R152 R153 R156-R165 R168 R176-R185 R188 R190 R192 R203 R208 R210-R212 R216 R218 R221 R222 R224-R228 R230-R232 R235-R239 R243 R274 R277 R293 = SR0402
R17-R24 R65 R250-R252 R260-R267 = SR0805
R174 R175 = HSR0402
RN1-RN5 = SRN8-0804
S1 = DSW4-LP
S2 = PSW3-RA
S3-S10 = SW4-PUSH
T1 T2 = STFM16-50-285
U2 U5 = DFN2510P10E
U3 U4 = MLF32-050-0505LB
U6 U19 U20 = SOIC8N
U7 = BGA96-32-1609F
U8 = SOP28-50-300
U9 = SGM8903
U10 = TO-252
U11 = LASER3-1214
U12 = FMS6141_SC70
U13 U18 = SOT223A
U14 = SOT23A-6L
U15 = QFP216HC-040-2424L
U16 = SO8W
U17 = SOP8-50-173
U21 = SOP48-20-720B
U22 = FN24-050-0404LH
U23 = SOP14-50-150
X1 = XTAL2-200A
X2 = SX2-1205

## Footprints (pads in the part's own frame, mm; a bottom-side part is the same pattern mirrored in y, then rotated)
1SMART18-6240
  round 3.2 hole 3.2 unplated: (-29,10) (-29,-10) (29,10) (29,-10)
  rect 1.397x2.159 hole 1.016: 1(6.88,-19.05)
  oval 1.397x2.159 hole 1.016: 2(4.34,-19.05) 3(1.8,-19.05) 4(-0.74,-19.05) 5(6.88,19.05) 6(4.34,19.05) 7(1.8,19.05) 8(-0.74,19.05) 9(17.04,-19.05) 10(14.5,-19.05) 11(11.96,-19.05) 12(9.42,-19.05) 13(17.04,19.05) 14(14.5,19.05) 15(11.96,19.05) 16(9.42,19.05)
  oval 2.159x1.397 hole 1.016: 17(-4.55,-16.51) 18(-4.55,-19.05)
  round 3.81 hole 2.286: 19(29,0) 20(-29,0)
BGA96-32-1609F
  round 0.356 smd: A1(-6,-3.2) A2(-6,-2.4) A3(-6,-1.6) A7(-6,1.6) A8(-6,2.4) A9(-6,3.2) B1(-5.2,-3.2) B2(-5.2,-2.4) B3(-5.2,-1.6) B7(-5.2,1.6) B8(-5.2,2.4) B9(-5.2,3.2) C1(-4.4,-3.2) C2(-4.4,-2.4) C3(-4.4,-1.6) C7(-4.4,1.6) C8(-4.4,2.4) C9(-4.4,3.2) D1(-3.6,-3.2) D2(-3.6,-2.4) D3(-3.6,-1.6) D7(-3.6,1.6) D8(-3.6,2.4) D9(-3.6,3.2) E1(-2.8,-3.2) E2(-2.8,-2.4) E3(-2.8,-1.6) E7(-2.8,1.6) E8(-2.8,2.4) E9(-2.8,3.2) F1(-2,-3.2) F2(-2,-2.4) F3(-2,-1.6) F7(-2,1.6) F8(-2,2.4) F9(-2,3.2) G1(-1.2,-3.2) G2(-1.2,-2.4) G3(-1.2,-1.6) G7(-1.2,1.6) G8(-1.2,2.4) G9(-1.2,3.2) H1(-0.4,-3.2) H2(-0.4,-2.4) H3(-0.4,-1.6) H7(-0.4,1.6) H8(-0.4,2.4) H9(-0.4,3.2) J1(0.4,-3.2) J2(0.4,-2.4) J3(0.4,-1.6) J7(0.4,1.6) J8(0.4,2.4) J9(0.4,3.2) K1(1.2,-3.2) K2(1.2,-2.4) K3(1.2,-1.6) K7(1.2,1.6) K8(1.2,2.4) K9(1.2,3.2) L1(2,-3.2) L2(2,-2.4) L3(2,-1.6) L7(2,1.6) L8(2,2.4) L9(2,3.2) M1(2.8,-3.2) M2(2.8,-2.4) M3(2.8,-1.6) M7(2.8,1.6) M8(2.8,2.4) M9(2.8,3.2) N1(3.6,-3.2) N2(3.6,-2.4) N3(3.6,-1.6) N7(3.6,1.6) N8(3.6,2.4) N9(3.6,3.2) P1(4.4,-3.2) P2(4.4,-2.4) P3(4.4,-1.6) P7(4.4,1.6) P8(4.4,2.4) P9(4.4,3.2) R1(5.2,-3.2) R2(5.2,-2.4) R3(5.2,-1.6) R7(5.2,1.6) R8(5.2,2.4) R9(5.2,3.2) T1(6,-3.2) T2(6,-2.4) T3(6,-1.6) T7(6,1.6) T8(6,2.4) T9(6,3.2)
CAP2-300-240
  rect 1.778x1.778 hole 0.914: 1(-3.81,0)
  round 1.778 hole 0.914: 2(3.81,0)
CAPC2-79-217
  oval 1.219x1.778 hole 0.889: 1(0,0) 2(2,0)
CAPC2-100-200
  rect 1.397x1.778 hole 0.813: 1(-1.27,0)
  oval 1.397x1.778 hole 0.813: 2(1.27,0)
CAPC2-100-250
  rect 1.397x1.778 hole 0.813: 1(-1.27,0)
  oval 1.397x1.778 hole 0.813: 2(1.27,0)
DB9-2RF
  rect 1.524x1.524 hole 1.016: 1(5.486,1.448)
  round 1.524 hole 1.016: 2(2.743,1.448) 3(0,1.448) 4(-2.743,1.448) 5(-5.486,1.448) 6(4.115,-1.448) 7(1.372,-1.448) 8(-1.372,-1.448) 9(-4.115,-1.448)
  round 4.572 hole 3.175: 10(-12.497,0) 11(12.497,0)
DFN2510P10E
  oval 0.254x0.813 smd: 1(-1,-0.525) 5(1,-0.525) 6(1,0.525) 10(-1,0.525)
  oval 0.229x0.813 smd: 2(-0.5,-0.525) 4(0.5,-0.525) 7(0.5,0.525) 9(-0.5,0.525)
  oval 0.356x0.813 smd: 3(0,-0.525) 8(0,0.525)
DL-E40321BYR2-1W
  round 1.524 hole 1.016: (-13.97,3.76) (-13.97,-3.76) (13.97,3.76) (13.97,-3.76) 2(-6.35,-3.76) 3(-3.81,-3.76) 4(-1.27,-3.76) 5(1.27,-3.76) 6(3.81,-3.76) 7(6.35,-3.76) 8(8.89,-3.76) 9(8.89,3.76) 10(6.35,3.76) 11(3.81,3.76) 12(1.27,3.76) 13(-1.27,3.76) 14(-3.81,3.76) 15(-6.35,3.76) 16(-8.89,3.76)
  rect 1.524x1.524 hole 1.016: 1(-8.89,-3.76)
DSW4-LP
  rect 1.397x1.397 hole 0.813: 1(-1.27,-3.81)
  round 1.397 hole 0.813: 2(1.27,-3.81) 3(1.27,3.81) 4(-1.27,3.81)
FMS6141_SC70
  rect 0.356x1.143 smd: 1(-0.65,-1) 2(0,-1) 3(0.65,-1) 4(0.65,1) 5(-0.65,1)
FN24-050-0404LH
  oval 0.254x0.889 smd: 1(-1.25,-2) 2(-0.75,-2) 3(-0.25,-2) 4(0.25,-2) 5(0.75,-2) 6(1.25,-2) 13(1.25,2) 14(0.75,2) 15(0.25,2) 16(-0.25,2) 17(-0.75,2) 18(-1.25,2)
  oval 0.889x0.254 smd: 7(2,-1.25) 8(2,-0.75) 9(2,-0.25) 10(2,0.25) 11(2,0.75) 12(2,1.25) 19(-2,1.25) 20(-2,0.75) 21(-2,0.25) 22(-2,-0.25) 23(-2,-0.75) 24(-2,-1.25)
  rect 2.667x2.667 smd: 25(0,0)
HOLE138-8STAR
  round 3.505 hole 3.505 unplated: (0,0)
  round 0.711 hole 0.305: 1(-3.131,0) 2(-2.214,-2.214) 3(0,-3.131) 4(2.214,-2.214) 5(3.131,0) 6(2.214,2.214) 7(0,3.131) 8(-2.214,2.214)
HSC0402
  rect 0.508x0.508 smd: 1(-0.406,0) 2(0.406,0)
HSL0402
  rect 0.635x0.508 smd: 1(-0.508,0) 2(0.508,0)
HSL1007
  rect 0.914x1.626 smd: 1(-1.1,0) 2(1.1,0)
HSOD323A
  rect 1.118x0.508 smd: 1(1.372,0) 2(-1.372,0)
HSR0402
  rect 0.508x0.508 smd: 1(-0.406,0) 2(0.406,0)
ID-BOARD
  round 1.016 smd: 1(0,0)
IDC10-DTM0
  rect 1.524x1.524 hole 1.016: 1(-5.08,1.27)
  round 1.524 hole 1.016: 2(-2.54,1.27) 3(0,1.27) 4(2.54,1.27) 5(5.08,1.27) 6(-5.08,-1.27) 7(-2.54,-1.27) 8(0,-1.27) 9(2.54,-1.27) 10(5.08,-1.27)
IDC20-DTM1
  rect 1.397x1.397 hole 1.016: 1(-11.43,1.27)
  round 1.397 hole 1.016: 2(-8.89,1.27) 3(-6.35,1.27) 4(-3.81,1.27) 5(-1.27,1.27) 6(1.27,1.27) 7(3.81,1.27) 8(6.35,1.27) 9(8.89,1.27) 10(11.43,1.27) 11(-11.43,-1.27) 12(-8.89,-1.27) 13(-6.35,-1.27) 14(-3.81,-1.27) 15(-1.27,-1.27) 16(1.27,-1.27) 17(3.81,-1.27) 18(6.35,-1.27) 19(8.89,-1.27) 20(11.43,-1.27)
JTDA18250
  oval 1.778x2.54 hole 1.016x1.778: 1(-11.17,-7.5) 2(-11.17,7.5)
  oval 1.778x5.08 hole 1.27x4.572: 3(-14.87,7.5) 4(-14.87,-7.5)
  oval 3.302x1.778 hole 2.54x1.016: 5(-9.25,-13.675) 6(9.25,-13.675) 7(9.25,13.675) 8(-9.25,13.675)
LASER3-1214
  round 2.032 hole 2.032 unplated: (-4.6,2.1) (0,-3.9) (4.6,2.1)
  rect 1.397x1.397 hole 0.813: 1(-2.54,0)
  round 1.397 hole 0.813: 2(0,0) 3(2.54,0)
LED
  rect 1.397x1.397 hole 0.914: 1(0,1.27)
  round 1.397 hole 0.914: 2(0,-1.27)
MJ8-RLY
  round 3.429 hole 3.429 unplated: (-2.794,2.54) (9.906,2.54)
  round 1.27 hole 0.914: 1(0,0) 2(1.016,-1.778) 3(2.032,0) 4(3.048,-1.778) 5(4.064,0) 6(5.08,-1.778) 7(6.096,0) 8(7.112,-1.778) 9(-3.302,-6.604) 10(-1.016,-6.604) 11(8.128,-6.604) 12(10.414,-6.604)
MLF32-050-0505LB
  oval 0.254x0.635 smd: 1(-1.75,-2.362) 8(1.75,-2.362) 17(1.75,2.362) 24(-1.75,2.362)
  rect 0.254x0.635 smd: 2(-1.25,-2.362) 3(-0.75,-2.362) 4(-0.25,-2.362) 5(0.25,-2.362) 6(0.75,-2.362) 7(1.25,-2.362) 18(1.25,2.362) 19(0.75,2.362) 20(0.25,2.362) 21(-0.25,2.362) 22(-0.75,2.362) 23(-1.25,2.362)
  oval 0.635x0.254 smd: 9(2.362,-1.75) 16(2.362,1.75) 25(-2.362,1.75) 32(-2.362,-1.75)
  rect 0.635x0.254 smd: 10(2.362,-1.25) 11(2.362,-0.75) 12(2.362,-0.25) 13(2.362,0.25) 14(2.362,0.75) 15(2.362,1.25) 26(-2.362,1.25) 27(-2.362,0.75) 28(-2.362,0.25) 29(-2.362,-0.25) 30(-2.362,-0.75) 31(-2.362,-1.25)
  rect 3.175x3.175 smd: 33(0,0)
PMR0103-98TQ
  rect 1.524x1.524 hole 1.016: 1(2.5,0)
  round 1.524 hole 1.016: 2(0,0) 3(-2.5,0)
PSW3-RA
  rect 2.54x2.54 hole 1.524: 1(0,0)
  round 2.54 hole 1.524: 2(7.079,0) 3(14.158,0)
PWC0103-M-C
  rect 2.54x4.572 hole 1.016: 1(0,0)
  oval 2.54x5.08 hole 1.016: 2(-6,0)
  oval 4.572x2.54 hole 1.016: 3(-3.2,4.8)
QFP216HC-040-2424L
  rect 0.305x1.397 smd: 1(-10.65,-12.71) 54(10.65,-12.71) 109(10.65,12.71) 162(-10.65,12.71)
  rect 0.203x1.397 smd: 2(-10.2,-12.71) 3(-9.8,-12.71) 4(-9.4,-12.71) 5(-9,-12.71) 6(-8.6,-12.71) 7(-8.2,-12.71) 8(-7.8,-12.71) 9(-7.4,-12.71) 10(-7,-12.71) 11(-6.6,-12.71) 12(-6.2,-12.71) 13(-5.8,-12.71) 14(-5.4,-12.71) 15(-5,-12.71) 16(-4.6,-12.71) 17(-4.2,-12.71) 18(-3.8,-12.71) 19(-3.4,-12.71) 20(-3,-12.71) 21(-2.6,-12.71) 22(-2.2,-12.71) 23(-1.8,-12.71) 24(-1.4,-12.71) 25(-1,-12.71) 26(-0.6,-12.71) 27(-0.2,-12.71) 28(0.2,-12.71) 29(0.6,-12.71) 30(1,-12.71) 31(1.4,-12.71) 32(1.8,-12.71) 33(2.2,-12.71) 34(2.6,-12.71) 35(3,-12.71) 36(3.4,-12.71) 37(3.8,-12.71) 38(4.2,-12.71) 39(4.6,-12.71) 40(5,-12.71) 41(5.4,-12.71) 42(5.8,-12.71) 43(6.2,-12.71) 44(6.6,-12.71) 45(7,-12.71) 46(7.4,-12.71) 47(7.8,-12.71) 48(8.2,-12.71) 49(8.6,-12.71) 50(9,-12.71) 51(9.4,-12.71) 52(9.8,-12.71) 53(10.2,-12.71) 110(10.2,12.71) 111(9.8,12.71) 112(9.4,12.71) 113(9,12.71) 114(8.6,12.71) 115(8.2,12.71) 116(7.8,12.71) 117(7.4,12.71) 118(7,12.71) 119(6.6,12.71) 120(6.2,12.71) 121(5.8,12.71) 122(5.4,12.71) 123(5,12.71) 124(4.6,12.71) 125(4.2,12.71) 126(3.8,12.71) 127(3.4,12.71) 128(3,12.71) 129(2.6,12.71) 130(2.2,12.71) 131(1.8,12.71) 132(1.4,12.71) 133(1,12.71) 134(0.6,12.71) 135(0.2,12.71) 136(-0.2,12.71) 137(-0.6,12.71) 138(-1,12.71) 139(-1.4,12.71) 140(-1.8,12.71) 141(-2.2,12.71) 142(-2.6,12.71) 143(-3,12.71) 144(-3.4,12.71) 145(-3.8,12.71) 146(-4.2,12.71) 147(-4.6,12.71) 148(-5,12.71) 149(-5.4,12.71) 150(-5.8,12.71) 151(-6.2,12.71) 152(-6.6,12.71) 153(-7,12.71) 154(-7.4,12.71) 155(-7.8,12.71) 156(-8.2,12.71) 157(-8.6,12.71) 158(-9,12.71) 159(-9.4,12.71) 160(-9.8,12.71) 161(-10.2,12.71)
  rect 1.397x0.305 smd: 55(12.71,-10.65) 108(12.71,10.65) 163(-12.71,10.65) 216(-12.71,-10.65)
  rect 1.397x0.203 smd: 56(12.71,-10.2) 57(12.71,-9.8) 58(12.71,-9.4) 59(12.71,-9) 60(12.71,-8.6) 61(12.71,-8.2) 62(12.71,-7.8) 63(12.71,-7.4) 64(12.71,-7) 65(12.71,-6.6) 66(12.71,-6.2) 67(12.71,-5.8) 68(12.71,-5.4) 69(12.71,-5) 70(12.71,-4.6) 71(12.71,-4.2) 72(12.71,-3.8) 73(12.71,-3.4) 74(12.71,-3) 75(12.71,-2.6) 76(12.71,-2.2) 77(12.71,-1.8) 78(12.71,-1.4) 79(12.71,-1) 80(12.71,-0.6) 81(12.71,-0.2) 82(12.71,0.2) 83(12.71,0.6) 84(12.71,1) 85(12.71,1.4) 86(12.71,1.8) 87(12.71,2.2) 88(12.71,2.6) 89(12.71,3) 90(12.71,3.4) 91(12.71,3.8) 92(12.71,4.2) 93(12.71,4.6) 94(12.71,5) 95(12.71,5.4) 96(12.71,5.8) 97(12.71,6.2) 98(12.71,6.6) 99(12.71,7) 100(12.71,7.4) 101(12.71,7.8) 102(12.71,8.2) 103(12.71,8.6) 104(12.71,9) 105(12.71,9.4) 106(12.71,9.8) 107(12.71,10.2) 164(-12.71,10.2) 165(-12.71,9.8) 166(-12.71,9.4) 167(-12.71,9) 168(-12.71,8.6) 169(-12.71,8.2) 170(-12.71,7.8) 171(-12.71,7.4) 172(-12.71,7) 173(-12.71,6.6) 174(-12.71,6.2) 175(-12.71,5.8) 176(-12.71,5.4) 177(-12.71,5) 178(-12.71,4.6) 179(-12.71,4.2) 180(-12.71,3.8) 181(-12.71,3.4) 182(-12.71,3) 183(-12.71,2.6) 184(-12.71,2.2) 185(-12.71,1.8) 186(-12.71,1.4) 187(-12.71,1) 188(-12.71,0.6) 189(-12.71,0.2) 190(-12.71,-0.2) 191(-12.71,-0.6) 192(-12.71,-1) 193(-12.71,-1.4) 194(-12.71,-1.8) 195(-12.71,-2.2) 196(-12.71,-2.6) 197(-12.71,-3) 198(-12.71,-3.4) 199(-12.71,-3.8) 200(-12.71,-4.2) 201(-12.71,-4.6) 202(-12.71,-5) 203(-12.71,-5.4) 204(-12.71,-5.8) 205(-12.71,-6.2) 206(-12.71,-6.6) 207(-12.71,-7) 208(-12.71,-7.4) 209(-12.71,-7.8) 210(-12.71,-8.2) 211(-12.71,-8.6) 212(-12.71,-9) 213(-12.71,-9.4) 214(-12.71,-9.8) 215(-12.71,-10.2)
  rect 8.382x8.382 smd: 217(0,0)
SC0402
  rect 0.508x0.508 smd: 1(-0.406,0) 2(0.406,0)
SC0603
  rect 0.762x0.813 smd: 1(-0.699,0) 2(0.699,0)
SC0805
  rect 0.991x1.27 smd: 1(-0.813,0) 2(0.813,0)
SC1206
  rect 1.295x1.651 smd: 1(-1.346,0) 2(1.346,0)
SCAPC2-280-327
  rect 4.115x2.184 smd: 1(-3.55,0) 2(3.55,0)
SD0805-LED
  rect 1.27x1.397 smd: 1(-1.016,0) 2(1.016,0)
SEN3-100C
  rect 1.27x1.27 hole 0.813: 1(-2.54,0)
  round 1.27 hole 0.813: 2(0,0) 3(2.54,0)
SF6127
  rect 2.286x3.175 smd: 1(-2.54,0) 2(2.54,0)
SGM8903
  rect 0.356x1.524 smd: 1(-1.95,-2.921) 2(-1.3,-2.921) 3(-0.65,-2.921) 4(0,-2.921) 5(0.65,-2.921) 6(1.3,-2.921) 7(1.95,-2.921) 8(1.95,2.921) 9(1.3,2.921) 10(0.65,2.921) 11(0,2.921) 12(-0.65,2.921) 13(-1.3,2.921) 14(-1.95,2.921)
SIP-1P
  round 1.651 hole 0.914: 1(0,0)
SIP-4P-100
  rect 1.524x1.524 hole 1.016: 1(3.75,0)
  round 1.524 hole 1.016: 2(1.25,0) 3(-1.25,0) 4(-3.75,0)
SIP-6P-100
  rect 1.524x1.524 hole 1.016: 1(6.25,0)
  round 1.524 hole 1.016: 2(3.75,0) 3(1.25,0) 4(-1.25,0) 5(-3.75,0) 6(-6.25,0)
SIP-8P-98
  rect 1.778x2.286 hole 1.27: 1(0,0)
  oval 1.778x2.286 hole 1.27: 2(2.5,0) 3(5,0) 4(7.5,0) 5(10,0) 6(12.5,0) 7(15,0) 8(17.5,0)
SIP-10P_FP
  oval 1.168x1.778 hole 0.914: 1(0,0) 2(2,0) 3(4,0) 4(6,0) 5(8,0) 6(10,0) 7(12,0) 8(14,0) 9(16,0) 10(18,0)
SL0402
  rect 0.483x0.508 smd: 1(-0.394,0) 2(0.394,0)
SL0603
  rect 0.711x0.813 smd: 1(-0.74,0) 2(0.74,0)
SL0603A
  rect 0.889x1.016 smd: 1(-0.762,0) 2(0.762,0)
SL0805
  rect 0.94x1.27 smd: 1(-0.851,0) 2(0.851,0)
SL1206
  rect 1.295x1.651 smd: 1(-1.346,0) 2(1.346,0)
SL1210
  rect 1.295x2.413 smd: 1(-1.346,0) 2(1.346,0)
SL1806
  rect 1.651x1.905 smd: 1(-2.032,0) 2(2.032,0)
SL2828
  rect 7.366x2.667 smd: 1(0,-2.325) 2(0,2.325)
SMD0805-050
  rect 1.016x1.778 smd: 1(-1,0) 2(1,0)
SO8W
  rect 0.635x2.032 smd: 1(-1.905,-3.902) 2(-0.635,-3.902) 3(0.635,-3.902) 4(1.905,-3.902) 5(1.905,3.902) 6(0.635,3.902) 7(-0.635,3.902) 8(-1.905,3.902)
SOIC8N
  rect 0.635x1.905 smd: 1(-1.905,-2.6) 2(-0.635,-2.6) 3(0.635,-2.6) 4(1.905,-2.6) 5(1.905,2.6) 6(0.635,2.6) 7(-0.635,2.6) 8(-1.905,2.6)
  rect 3.505x2.616 smd: 9(0,0)
SOP8-50-173
  rect 0.635x1.778 smd: 1(-1.905,-2.667) 2(-0.635,-2.667) 3(0.635,-2.667) 4(1.905,-2.667) 5(1.905,2.667) 6(0.635,2.667) 7(-0.635,2.667) 8(-1.905,2.667)
SOP14-50-150
  rect 0.635x1.905 smd: 1(-3.81,-2.667) 2(-2.54,-2.667) 3(-1.27,-2.667) 4(0,-2.667) 5(1.27,-2.667) 6(2.54,-2.667) 7(3.81,-2.667) 8(3.81,2.667) 9(2.54,2.667) 10(1.27,2.667) 11(0,2.667) 12(-1.27,2.667) 13(-2.54,2.667) 14(-3.81,2.667)
SOP28-50-300
  rect 0.635x1.778 smd: 1(-8.255,-4.699) 2(-6.985,-4.699) 3(-5.715,-4.699) 4(-4.445,-4.699) 5(-3.175,-4.699) 6(-1.905,-4.699) 7(-0.635,-4.699) 8(0.635,-4.699) 9(1.905,-4.699) 10(3.175,-4.699) 11(4.445,-4.699) 12(5.715,-4.699) 13(6.985,-4.699) 14(8.255,-4.699) 15(8.255,4.699) 16(6.985,4.699) 17(5.715,4.699) 18(4.445,4.699) 19(3.175,4.699) 20(1.905,4.699) 21(0.635,4.699) 22(-0.635,4.699) 23(-1.905,4.699) 24(-3.175,4.699) 25(-4.445,4.699) 26(-5.715,4.699) 27(-6.985,4.699) 28(-8.255,4.699)
SOP48-20-720B
  rect 0.254x1.473 smd: 1(-5.75,-9.802) 2(-5.25,-9.802) 3(-4.75,-9.802) 4(-4.25,-9.802) 5(-3.75,-9.802) 6(-3.25,-9.802) 7(-2.75,-9.802) 8(-2.25,-9.802) 9(-1.75,-9.802) 10(-1.25,-9.802) 11(-0.75,-9.802) 12(-0.25,-9.802) 13(0.25,-9.802) 14(0.75,-9.802) 15(1.25,-9.802) 16(1.75,-9.802) 17(2.25,-9.802) 18(2.75,-9.802) 19(3.25,-9.802) 20(3.75,-9.802) 21(4.25,-9.802) 22(4.75,-9.802) 23(5.25,-9.802) 24(5.75,-9.802) 25(5.75,9.802) 26(5.25,9.802) 27(4.75,9.802) 28(4.25,9.802) 29(3.75,9.802) 30(3.25,9.802) 31(2.75,9.802) 32(2.25,9.802) 33(1.75,9.802) 34(1.25,9.802) 35(0.75,9.802) 36(0.25,9.802) 37(-0.25,9.802) 38(-0.75,9.802) 39(-1.25,9.802) 40(-1.75,9.802) 41(-2.25,9.802) 42(-2.75,9.802) 43(-3.25,9.802) 44(-3.75,9.802) 45(-4.25,9.802) 46(-4.75,9.802) 47(-5.25,9.802) 48(-5.75,9.802)
